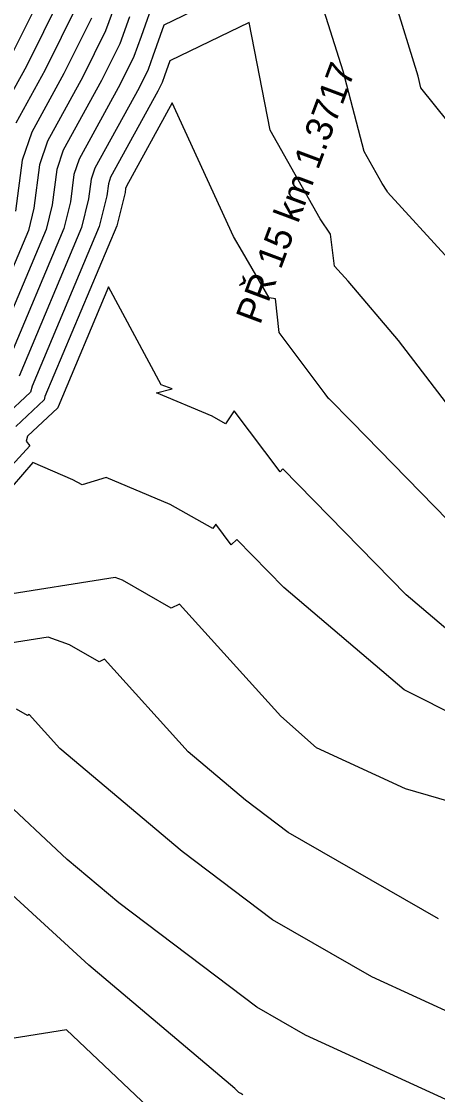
# Model space of a CAD drawing. Extents: x -549394 to -546608, y -1037055 to -1033629.
# Drawn here: x -548719.5 to -548577.2, y -1034491.4 to -1034124.2 of the extents above; entities that cross this region are included whole.
import ezdxf

# ---------------------------------------------------------------- set-up
doc = ezdxf.new("R2010")
doc.units = 0
for name, color, linetype in [('hlavni_vrst', 7, 'Continuous'), ('norm_vrst', 7, 'Continuous'), ('x_popis_pricne_rezy_C21', 7, 'Continuous')]:
    doc.layers.add(name, color=color, linetype=linetype)

msp = doc.modelspace()

# ---------------------------------------------------------------- linework, layer by layer
at = {"layer": 'hlavni_vrst'}
for p, q in [((-548583.87, -1034143.01), (-548599.61, -1034091.31)), ((-548705.2, -1034114.25), (-548717.77, -1034139.57)), ((-548672.9, -1034113.25), (-548678.51, -1034129.39)), ((-548678.51, -1034129.39), (-548681.01, -1034136.28)), ((-548681.01, -1034136.28), (-548685.68, -1034145.68)), ((-548717.77, -1034139.57), (-548726.75, -1034155.89)), ((-548582.87, -1034146.92), (-548583.87, -1034143.01)), ((-548685.68, -1034145.68), (-548699.78, -1034171.31)), ((-548550.64, -1034187.34), (-548582.87, -1034146.92)), ((-548699.78, -1034171.31), (-548701.52, -1034176.54)), ((-548701.52, -1034176.54), (-548702.74, -1034185.97)), ((-548702.74, -1034185.97), (-548704.96, -1034195.08)), ((-548704.96, -1034195.08), (-548724.74, -1034242.04)), ((-548715.59, -1034275.15), (-548726.21, -1034287.49)), ((-548701.85, -1034281.06), (-548715.59, -1034275.15)), ((-548690.48, -1034280.2), (-548698.68, -1034282.78)), ((-548668.6, -1034289.46), (-548690.48, -1034280.2)), ((-548698.68, -1034282.78), (-548701.85, -1034281.06)), ((-548654.02, -1034297.71), (-548668.6, -1034289.46)), ((-548653.01, -1034296.2), (-548654.02, -1034297.71)), ((-548647.73, -1034303.24), (-548653.01, -1034296.2)), ((-548645.86, -1034301.43), (-548647.73, -1034303.24)), ((-548629.71, -1034317.92), (-548645.86, -1034301.43)), ((-548588.64, -1034352.94), (-548629.71, -1034317.92)), ((-548549.58, -1034372.48), (-548588.64, -1034352.94)), ((-548696.43, -1034447.05), (-548722.62, -1034422.98)), ((-548646.53, -1034489.27), (-548696.43, -1034447.05)), ((-548645.09, -1034490.62), (-548646.53, -1034489.27)), ((-548644.45, -1034491.01), (-548645.09, -1034490.62)), ((-548643.76, -1034491.42), (-548644.45, -1034491.01))]:
    msp.add_line(p, q, dxfattribs=at)
at = {"layer": 'norm_vrst'}
for p, q in [((-548609.42, -1034141.28), (-548621.22, -1034103.91)), ((-548710.04, -1034109.84), (-548724.19, -1034138.35)), ((-548645.87, -1034113.4), (-548670.81, -1034125.46)), ((-548700.36, -1034118.65), (-548711.35, -1034140.79)), ((-548686.48, -1034115.91), (-548690.69, -1034127.47)), ((-548682.49, -1034122.65), (-548685.85, -1034131.87)), ((-548695.53, -1034123.06), (-548704.93, -1034142.01)), ((-548670.81, -1034125.46), (-548674.52, -1034136.13)), ((-548641.66, -1034124.58), (-548668.72, -1034137.68)), ((-548634.4, -1034161.46), (-548641.66, -1034124.58)), ((-548690.69, -1034127.47), (-548698.52, -1034143.23)), ((-548685.85, -1034131.87), (-548692.1, -1034144.46)), ((-548674.52, -1034136.13), (-548676.17, -1034140.69)), ((-548711.35, -1034140.79), (-548721.36, -1034158.98)), ((-548676.17, -1034140.69), (-548679.26, -1034146.9)), ((-548668.72, -1034137.68), (-548670.53, -1034142.88)), ((-548704.93, -1034142.01), (-548715.96, -1034162.06)), ((-548698.52, -1034143.23), (-548710.57, -1034165.14)), ((-548692.1, -1034144.46), (-548705.17, -1034168.22)), ((-548670.53, -1034142.88), (-548671.34, -1034145.09)), ((-548602.28, -1034168.75), (-548609.42, -1034141.28)), ((-548679.26, -1034146.9), (-548694.38, -1034174.39)), ((-548672.84, -1034148.12), (-548688.99, -1034177.47)), ((-548671.34, -1034145.09), (-548672.84, -1034148.12)), ((-548667.92, -1034152.07), (-548683.59, -1034180.56)), ((-548647.02, -1034197.79), (-548667.92, -1034152.07)), ((-548715.96, -1034162.06), (-548719.19, -1034171.72)), ((-548617.38, -1034191.77), (-548634.4, -1034161.46)), ((-548710.57, -1034165.14), (-548713.3, -1034173.33)), ((-548705.17, -1034168.22), (-548707.41, -1034174.93)), ((-548596.19, -1034179.64), (-548602.28, -1034168.75)), ((-548719.19, -1034171.72), (-548721.44, -1034189.15)), ((-548713.3, -1034173.33), (-548715.2, -1034188.09)), ((-548707.41, -1034174.93), (-548708.97, -1034187.03)), ((-548694.38, -1034174.39), (-548695.63, -1034178.14)), ((-548688.99, -1034177.47), (-548689.75, -1034179.75)), ((-548695.63, -1034178.14), (-548696.51, -1034184.91)), ((-548689.75, -1034179.75), (-548690.28, -1034183.85)), ((-548683.86, -1034181.35), (-548684.05, -1034182.79)), ((-548683.59, -1034180.56), (-548683.86, -1034181.35)), ((-548594.41, -1034182.27), (-548596.19, -1034179.64)), ((-548696.51, -1034184.91), (-548698.91, -1034194.76)), ((-548690.28, -1034183.85), (-548692.86, -1034194.44)), ((-548684.05, -1034182.79), (-548686.81, -1034194.12)), ((-548594.36, -1034182.69), (-548594.41, -1034182.27)), ((-548573.46, -1034205.49), (-548594.36, -1034182.69)), ((-548715.2, -1034188.09), (-548717.06, -1034195.72)), ((-548708.97, -1034187.03), (-548711.01, -1034195.4)), ((-548613.85, -1034197), (-548617.38, -1034191.77)), ((-548717.06, -1034195.72), (-548733.62, -1034235.04)), ((-548711.01, -1034195.4), (-548729.18, -1034238.54)), ((-548698.91, -1034194.76), (-548720.29, -1034245.54)), ((-548692.86, -1034194.44), (-548715.85, -1034249.04)), ((-548686.81, -1034194.12), (-548711.41, -1034252.54)), ((-548643.93, -1034203.01), (-548647.02, -1034197.79)), ((-548612.48, -1034207.99), (-548613.85, -1034197)), ((-548634.8, -1034218.77), (-548643.93, -1034203.01)), ((-548607.79, -1034213.12), (-548612.48, -1034207.99)), ((-548590.6, -1034233.4), (-548607.79, -1034213.12)), ((-548689.68, -1034214.99), (-548706.96, -1034256.04)), ((-548671.73, -1034248.5), (-548689.68, -1034214.99)), ((-548632.63, -1034219.17), (-548634.8, -1034218.77)), ((-548631.36, -1034230.66), (-548632.63, -1034219.17)), ((-548615.63, -1034251.62), (-548631.36, -1034230.66)), ((-548572.99, -1034256.36), (-548590.6, -1034233.4)), ((-548716.35, -1034251.01), (-548725.39, -1034259.47)), ((-548715.85, -1034249.04), (-548716.35, -1034251.01)), ((-548673.3, -1034251.25), (-548667.97, -1034249.87)), ((-548667.97, -1034249.87), (-548671.73, -1034248.5)), ((-548711.71, -1034253.73), (-548721.4, -1034262.8)), ((-548711.41, -1034252.54), (-548711.71, -1034253.73)), ((-548654.22, -1034259.32), (-548673.3, -1034251.25)), ((-548614.38, -1034253.29), (-548615.63, -1034251.62)), ((-548614.34, -1034253.24), (-548614.38, -1034253.29)), ((-548606.49, -1034261.26), (-548614.34, -1034253.24)), ((-548707.07, -1034256.46), (-548717.41, -1034266.14)), ((-548706.96, -1034256.04), (-548707.07, -1034256.46)), ((-548646.69, -1034257.42), (-548649.7, -1034261.88)), ((-548631.06, -1034278.27), (-548646.69, -1034257.42)), ((-548649.7, -1034261.88), (-548654.22, -1034259.32)), ((-548553.29, -1034315.9), (-548606.49, -1034261.26)), ((-548716.55, -1034269.39), (-548730.73, -1034284.78)), ((-548717.41, -1034266.14), (-548717.89, -1034267.87)), ((-548717.89, -1034267.87), (-548716.55, -1034269.39)), ((-548630.1, -1034277.34), (-548631.06, -1034278.27)), ((-548587.9, -1034320.42), (-548630.1, -1034277.34)), ((-548687.4, -1034314.52), (-548740.71, -1034322.92)), ((-548684.92, -1034315.39), (-548687.4, -1034314.52)), ((-548668.27, -1034324.97), (-548684.92, -1034315.39)), ((-548571.43, -1034334.47), (-548587.9, -1034320.42)), ((-548665.39, -1034323.55), (-548668.27, -1034324.97)), ((-548630.74, -1034361.88), (-548665.39, -1034323.55)), ((-548710.3, -1034334.9), (-548740.22, -1034339.62)), ((-548703.04, -1034337.46), (-548710.3, -1034334.9)), ((-548692.84, -1034343.32), (-548703.04, -1034337.46)), ((-548691.08, -1034342.45), (-548692.84, -1034343.32)), ((-548662.5, -1034374.07), (-548691.08, -1034342.45)), ((-548717.42, -1034361.68), (-548721.16, -1034359.52)), ((-548716.77, -1034361.36), (-548717.42, -1034361.68)), ((-548706.28, -1034372.96), (-548716.77, -1034361.36)), ((-548618.59, -1034372.71), (-548630.74, -1034361.88)), ((-548664.52, -1034408.24), (-548706.28, -1034372.96)), ((-548642.83, -1034390.68), (-548662.5, -1034374.07)), ((-548588.13, -1034386.75), (-548618.59, -1034372.71)), ((-548703.81, -1034410.93), (-548730.72, -1034385.83)), ((-548557.36, -1034395.67), (-548588.13, -1034386.75)), ((-548628.29, -1034401.66), (-548642.83, -1034390.68)), ((-548576.92, -1034431.22), (-548628.29, -1034401.66)), ((-548633.63, -1034431.57), (-548664.52, -1034408.24)), ((-548686.2, -1034425.81), (-548703.81, -1034410.93)), ((-548638.98, -1034461.47), (-548686.2, -1034425.81)), ((-548599.62, -1034451.14), (-548633.63, -1034431.57)), ((-548563.3, -1034467.8), (-548599.62, -1034451.14)), ((-548622.32, -1034471.06), (-548638.98, -1034461.47)), ((-548704.09, -1034469.25), (-548770.74, -1034479.84)), ((-548669.67, -1034501.74), (-548704.09, -1034469.25)), ((-548556.48, -1034501.26), (-548622.32, -1034471.06))]:
    msp.add_line(p, q, dxfattribs=at)

# ---------------------------------------------------------------- texts
at = {"layer": 'x_popis_pricne_rezy_C21'}
msp.add_text('PŘ 15 km 1.3717', height=9.0627, rotation=69.4791, dxfattribs=at).set_placement((-548637.9, -1034228.29))

doc.saveas('drawing.dxf')
